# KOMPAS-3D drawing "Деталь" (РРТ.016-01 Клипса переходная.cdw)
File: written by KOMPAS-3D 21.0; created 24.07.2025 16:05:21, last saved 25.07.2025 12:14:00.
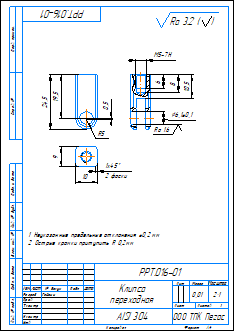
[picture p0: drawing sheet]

Sheet 1: A4, portrait

Document properties: Автор: User; Полное имя файла: C:\Users\User\Desktop\Ручной ротатор КД\Чертежи\РРТ.016-01 Клипса переходная.cdw; Знак неуказанной шероховатости: 4; Параметр неуказанной шероховатости: Ra 3.2; Масса: 0.009774

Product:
- Part/product: Деталь
    Масса: 0.009717
    Форматы листов документа: A4

Title block, sheet 1: Наименование: Клипса / переходная; designation: РРТ.016 - 01; Материал: AISI 304; Масса: 0,01; Количество листов документа: 1; organisation: ООО ТПК Пегас; Форматы листов документа: A4; stored path: C:\Users\User\Desktop\Ручной ротатор КД\Чертежи\РРТ.016 Клипса переходная.cdw; Разработал: Гайсин

Views: Спереди 1, Спереди, Проекционный вид 2, Проекционный вид 3, Местный разрез 1, Местный разрез 2
Referenced files in C:\Users\User\Desktop\Ручной ротатор КД\Модели КД\: РРТ.016 Клипса переходная.m3d, РРТ.016-01 Клипса переходная.m3d
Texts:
  Ra 1.6
  Ra 3.2
  Ra 3.2 ( )
Dimensions and other numbers on the sheet: 24,5; 19,5; 5; 0,5; 9; 10; 1; 2 фаски; 8; 6; -7Н; 10,5; 6,1±0,1; 2:1; 0,01

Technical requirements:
  Неуказанные предельные отклонения  0,2 мм
  Острые кромки притупить R 0,2мм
